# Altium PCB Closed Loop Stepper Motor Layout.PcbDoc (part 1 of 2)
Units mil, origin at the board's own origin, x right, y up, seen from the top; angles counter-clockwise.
Board outline 3560 x 2030 mil, 2 copper layers (Top Layer, Bottom Layer), stack 64.8 mil thick; 66 components, 54 nets, 285 pads, 203 vias.
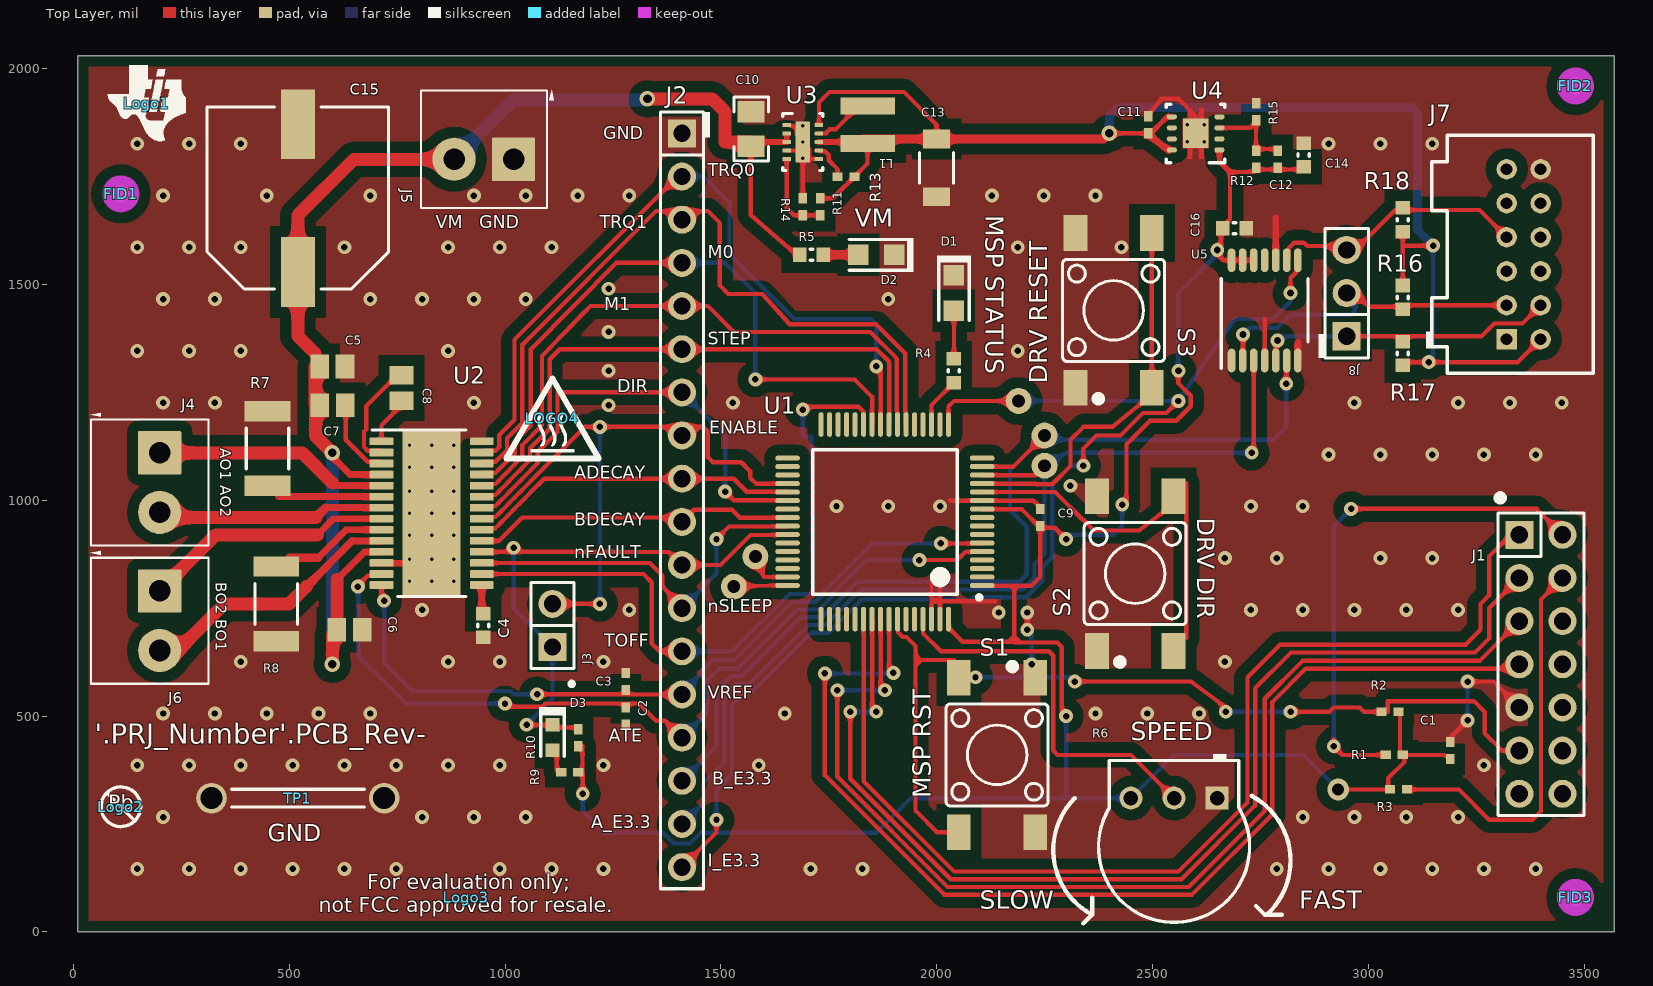
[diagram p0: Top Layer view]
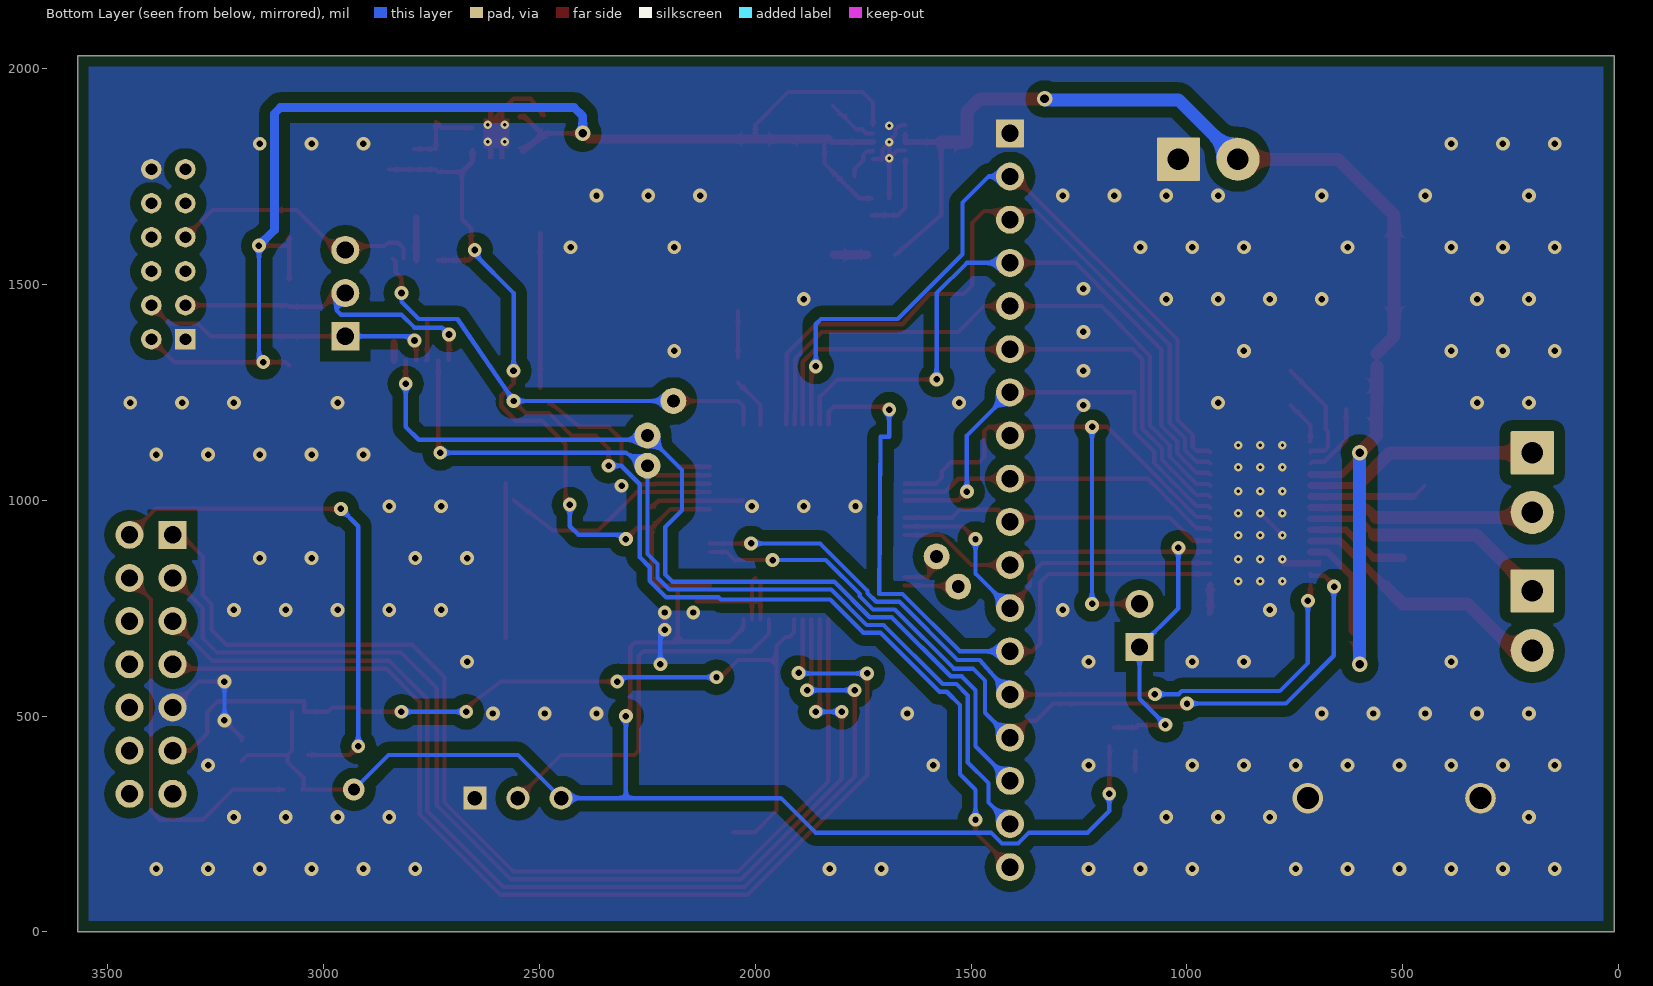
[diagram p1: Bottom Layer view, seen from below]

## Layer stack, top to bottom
Top Solder: solder mask 0.4, Solder Resist, Dk 3.5
Top Layer: signal copper 2.8
Dielectric1: core 59.2, FR-4, Dk 4.8
Bottom Layer: signal copper 2.8
Bottom Solder: solder mask 0.4, Solder Resist, Dk 3.5

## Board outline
10,0 10,2030 3570,2030 3570,0

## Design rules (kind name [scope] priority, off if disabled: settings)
AcuteAngle [All] p1: minimum=4.50000000000000E+0001 checktracksonly=FALSE
AssemblyTestPointUsage [All] p1: valid=2
BoardOutlineClearance BoardOutlineClearance_MountingHoles [OnCopper and InComponentClass('Mounting Holes')] p1: gap=40
BoardOutlineClearance BoardOutlineClearance_Poly [OnCopper and IsPoly] p2: gap=25
BoardOutlineClearance [OnCopper and Not InComponentClass('Logo') and not InComponentClass('FiducialMark') and not InRegion(1000,500,4000,800) and not InPoly] p3: gap=75
Clearance Clearance_Keepouts [((IsTrack Or IsArc) And Not InPoly) And IsFree and IsKeepOut vs ((IsTrack Or IsArc) And Not InPoly) And IsFree and IsKeepOut] p1: gap=0
Clearance Clearance_Poly [InPolygon] p2: gap=25
Clearance [All] p3: gap=7.87
ComponentClearance ComponentClearance_MountingHoles_FiducialMarks [InComponentClass('Mounting Holes') vs InComponentClass('FiducialMark')] p1: gap=50 collisioncheckmode=3 verticalgap=10 showdistances=FALSE
ComponentClearance ComponentClearance_Shunt [InComponentClass('Header') vs InComponentClass('Shunt')] p2: gap=0 collisioncheckmode=3 verticalgap=0 showdistances=FALSE
ComponentClearance ComponentClearance_Logo [InComponentClass('Logo')] p3: gap=50 collisioncheckmode=3 verticalgap=10 showdistances=FALSE
ComponentClearance ComponentClearance_ScrewToNut [(HasFootprint('NY PMS 440 0025 PH')) vs (HasFootprint('Keystone_1902C'))] p4: gap=5 collisioncheckmode=3 verticalgap=10 showdistances=FALSE
ComponentClearance ComponentClearance_MountingHoles [InComponentClass('Mounting Holes')] p5: gap=250 collisioncheckmode=3 verticalgap=100000 showdistances=FALSE
ComponentClearance ComponentClearance_SmallPassives [HasFootprint('0201*') or HasFootprint('0402*') or HasFootprint('0508') or HasFootprint('0603*') or HasFootprint('0612') or HasFootprint('0805*') or HasFootprint('0815*') or HasFootprint('0830*') or HasFootprint('1206*') or HasFootprint('1210*') or HasFootprint('1808*') or HasFootprint('1812*') or HasFootprint('1825*') or HasFootprint('2010*') or HasFootprint('2220*') or HasFootprint('2225*') or HasFootprint('2512*') or HasFootprint('2728*') or HasFootprint('3518*') vs HasFootprint('0201*') or HasFootprint('0402*') or HasFootprint('0508') or HasFootprint('0603*') or HasFootprint('0612') or HasFootprint('0805*') or HasFootprint('0815*') or HasFootprint('0830*') or HasFootprint('1206*') or HasFootprint('1210*') or HasFootprint('1808*') or HasFootprint('1812*') or HasFootprint('1825*') or HasFootprint('2010*') or HasFootprint('2220*') or HasFootprint('2225*') or HasFootprint('2512*') or HasFootprint('2728*') or HasFootprint('3518*')] p6: gap=14.96 collisioncheckmode=3 verticalgap=10 showdistances=FALSE
ComponentClearance ComponentClearance_THtoSMT [IsThruComponent vs IsSMTComponent] p7: gap=40 collisioncheckmode=3 verticalgap=30 showdistances=FALSE
ComponentClearance ComponentClearance_THtoTH [IsThruComponent vs IsThruComponent] p8: gap=30 collisioncheckmode=3 verticalgap=30 showdistances=FALSE
ComponentClearance [All] p9: gap=30 collisioncheckmode=3 verticalgap=10 showdistances=FALSE
DiffPairsRouting [All] p1: maxlimit=100 minlimit=10 mostfreqgap=10 toplayer_minwidth=15 toplayer_maxwidth=15 toplayer_prefwidth=15 bottomlayer_minwidth=15 bottomlayer_maxwidth=15 bottomlayer_prefwidth=15 maxuncoupledlength=1000
FabricationTestPointUsage TestPointUsage [All] p1: valid=2 allowmultiple=FALSE
FabricationTestpoint Testpoint [All] p1: side=3 testpointundercomponent=TRUE minsize=40 maxsize=100 preferedsize=60 minholesize=0 maxholesize=40 preferedholesize=32 testpointgrid=1 allowsidetop=TRUE allowsidebottom=TRUE usegrid=TRUE gridtolerance=0.01
FanoutControl Fanout_LCC [IsLCC] p1: bgadir=Out bgaviamode=Centered fanoutstyle=Auto fanoutdirection=Alternating viagrid=1 // Fanout_LCC (Default Rule)
FanoutControl Fanout_BGA [IsBGA] p2: bgadir=Out bgaviamode=Centered fanoutstyle=Auto fanoutdirection=Alternating viagrid=1 // Fanout_BGA (Default Rule)
FanoutControl Fanout_Default [All] p4: bgadir=Out bgaviamode=Centered fanoutstyle=Auto fanoutdirection=Alternating viagrid=1 // Fanout_Default (Default Rule)
FanoutControl Fanout_Small [(CompPinCount < 5)] p5: bgadir=Out bgaviamode=Centered fanoutstyle=Auto fanoutdirection=OutThenIn viagrid=1 // Fanout_Small (Default Rule)
HoleSize [All] p1: absolutevalues=TRUE maxlimit=251 minlimit=7.87 maxpercent=80.000 minpercent=20.000
MinimumAnnularRing MinimumAnnularRing_ThermalPadVias [IsVia and InAnyComponent] p1: minimumring=5.91
MinimumAnnularRing [All] p2: minimumring=8
MinimumSolderMaskSliver MinimumSolderMaskSliver_Logo [InComponentClass('Logo') vs InComponentClass('Logo')] p1: minsoldermaskwidth=0.7
MinimumSolderMaskSliver [All] p2: minsoldermaskwidth=3.94
PlaneConnect [All] p1: planeconnectstyle=Direct reliefexpansion=10 reliefentries=4 reliefconductorwidth=10 reliefairgap=10
PolygonConnect PolygonConnect_1 [All vs IsNamedPolygon('Top Layer-GND')] p1: connectstyle=Direct reliefconductorwidth=10 reliefentries=4 polygonreliefangle="90 Angle" airgapwidth=10
PolygonConnect [All] p2: connectstyle=Direct reliefconductorwidth=10 reliefentries=4 polygonreliefangle="90 Angle" airgapwidth=10
RoutingVias ThermalPadVias [IsVia and InAnyComponent] p1: holewidth=7.87 width=19.68 viastyle="Through Hole" minholewidth=7.87 minwidth=19.68 maxholewidth=12.99 maxwidth=23.62
RoutingVias [All] p2: holewidth=16 width=34 viastyle="Through Hole" minholewidth=7.87 minwidth=26 maxholewidth=40 maxwidth=65
SilkToBoardRegionClearance [Not ((IsComment or IsDesignator) And (Hide <> 'False')) and not InRegion(1000,500,4000,800)] p1:
SilkToSilkClearance SilkToSilkClearance_Pb-FreeLogo [(HasFootprint('Pb-Free_Overlay_Medium') OR HasFootprint('Pb-Free_Overlay_Small')) vs (HasFootprint('Pb-Free_Overlay_Medium') OR HasFootprint('Pb-Free_Overlay_Small'))] p1: silktosilkclearance=0
SilkToSilkClearance [All] p2: silktosilkclearance=4
SilkToSolderMaskClearance SilkToComponentPadClearance [IsPad and InAnycomponent] p1: minsilkscreentomaskgap=5 clearancetoexposedcopper=TRUE
SilkToSolderMaskClearance "Silk to Solder Mask Opening" [All] p2: minsilkscreentomaskgap=4 clearancetoexposedcopper=FALSE
SolderMaskExpansion [All] p1: expansion=1.97
Width [All] p1: maxlimit=100 minlimit=6 preferedwidth=10 checkconnectedcopper=TRUE
15 further rules are at their usual default settings.

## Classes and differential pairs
component class Header: J1 J2 J3 J8
component class "Closed Loop DRV8880_MSP430": C1 C2 C3 C4 C5 C6 C7 C8 C9 D1 D2 D3 J1 J2 J3 R1 R2 R3 R4 R5 R6 R7 R8 R9 R10 S1 S2 S3 U1 U2
component class "Closed Loop PWR&Encoder": 20 C10 C11 C12 C13 C14 C15 C16 J4 J5 J6 J7 J8 L1 R11 R12 R13 R14 R15 R16 R17 R18 Text TP1 U3 U4 U5
component class Logo: Logo1
component class "Closed Loop Last Sheet": FID1 FID2 FID3 Logo1 Logo2 Logo3 LOGO4 ZZ1 ZZ2 ZZ3 ZZ4
component class FiducialMark: FID1 FID2 FID3
component class AssemblyNote: ZZ1 ZZ2 ZZ3 ZZ4

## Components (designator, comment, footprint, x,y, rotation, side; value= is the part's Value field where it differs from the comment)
C1 "GRM155R61A104KA01D" 0402L 3190,420 r90 top
C2 "GRM155R61A104KA01D" 0402L 1280,500 r270 top
C3 "GRM155R61A104KA01D" 0402L 1280,580 r90 top
C4 "C0603C474K9RACTU" 0603L 950,710 r270 top
C5 "C0805C104K1RACTU" 0805L 600,1310 r0 top
C6 "C0805C104K1RACTU" 0805L 640,700 r0 top
C7 "0805YC474KAT2A" 0805L 600.47,1220 r180 top
C8 "GRM21BR71E104KA01L" 0805L 760,1260 r270 top
C9 "GRM155R61A104KA01D" 0402L 2240,960 r270 top
C10 "GRM21BR61E225KA12L" 0805_HV 1570,1860 r90 top
C11 "C1005X5R0J105M050BB" 0402L 2490,1870 r270 top
C12 "C1005C0G1H220J050BA" 0402L 2790,1790 r90 top
C13 "GRM31CR61A226ME19L" 1206_180 2000,1770 r270 top
C14 "GRM188R60J475KE19D" 0603L 2850,1800 r90 top
C15 "EEE-FK1J101P" SM_RADIAL_G 520,1700 r90 top
C16 "C0603C104K8RACTU" 0603L 2690,1630 r0 top
D1 "LTST-C171GKT" LED_LTST-C171 2040,1480 r90 top
D2 "LTST-C171GKT" LED_LTST-C171 1860,1568.7 r0 top
D3 "LTST-C190CKT" LED_LTST-C190_Red 1110,450 r90 top
FID1 "Fiducial" Fiducial10-20 110,1710 r0 top
FID2 "Fiducial" Fiducial10-20 3480,1960 r0 top
FID3 "Fiducial" Fiducial10-20 3480,80 r0 top
J1 "PEC07DAAN" CONN_PEC07DAAN 3400,620 r270 top
J2 "TSW-118-07-G-S" TSW-118-07-G-S 1410,1000 r270 top
J3 "Retry Mode DRV8880" CONN_90120-0122 1110,710 r90 top
J4 "AOUT" TERM_BLK_ED555-2DS 200,1110 r270 top
J5 "VM_GND" TERM_BLK_ED555-2DS 1020,1790 r180 top
J6 "BOUT" TERM_BLK_ED555-2DS 200,790 r270 top
J7 "B12B-PADSS-F(LF)(SN)" JST_B12B-PADSS-F 3360,1570 r90 top
J8 "TSW-103-07-G-S" TSW-103-07-G-S 2950,1480 r90 top
L1 "744025100" WE-TPC_2828 1840,1870 r270 top
Logo1 "Texas Instruments" TI_Symbol_Overlay_Small 170,1920 r0 top
Logo2 "Pb-Free Symbol" Pb-Free_Overlay_Small 110,290 r0 top
Logo3 "FCC disclaimer" FCC_disclaimer_stacked 910,80 r0 top
LOGO4 "CAUTION HOT SURFACE" IEC_HotSurface_Small 1110,1190 r0 top
R1 "ERJ-2GE0R00X" 0402L 3060,410 r0 top
R2 "CRCW04023K32FKED" 0402L 3050,510 r0 top
R3 "ERJ-2GE0R00X" 0402L 3070,330 r180 top
R4 "CRCW0603330RJNEA" 0603L 2040,1300 r270 top
R5 "CRCW060310K0JNEA" 0603L 1710,1568.7 r180 top
R6 "3352T-1-503LF" Bourns_3352T 2550,310 r180 top
R7 "CSRN2010FKR250" 2010L 450,1120 r270 top
R8 "CSRN2010FKR250" 2010L 470,760 r90 top
R9 "CRCW0402510RJNED" 0402L 1150,370 r0 top
R10 "CRCW04024K99FKED" 0402L 1170,450 r270 top
R11 "CRCW040280K6FKED" 0402L 1730,1680 r90 top
R12 "CRCW0402191KFKED" 0402L 2740,1790 r270 top
R13 "CRCW0402100KFKED" 0402L 1790,1750 r0 top
R14 "CRCW040215K4FKED" 0402L 1690,1680 r90 top
R15 "CRCW0402110KFKED" 0402L 2740,1900 r270 top
R16 "CRCW060310K0JNEA" 0603L 3080,1470 r90 top
R17 "CRCW060310K0JNEA" 0603L 3080,1340 r270 top
R18 "CRCW060310K0JNEA" 0603L 3080,1650 r270 top
S1 "4-1437565-1" SW_FSM4JSMA 2140,410 r0 top
S2 "4-1437565-1" SW_FSM4JSMA 2460,830 r180 top
S3 "4-1437565-1" SW_FSM4JSMA 2410,1440 r180 top
TP1 "D3082-05" Harwin_D3082-05 520,310 r180 top
U1 "MSP430F2617TPM" PM0064A_N 1880,950 r180 top
U2 "DRV8880PWPR" PWP0028C_N 830,970 r0 top
U3 "TPS62175DQCR" DQC0010A 1690,1830 r0 top
U4 "TPS73501DRBR" DRB0008A 2600,1850 r180 top
U5 "SN74LV4T125PWR" PW0014A_N 2760,1440 r90 top
ZZ1 "This Assembly Note is for PCB labels only" AssemblyNoteLabel 90,2270 r0 top
ZZ2 "These assemblies are ESD sensitive, ESD precautions shall be observed." AssemblyNote 90,2410 r0 top
ZZ3 "These assemblies must be clean and free from flux and all contaminants. Use of no clean flux is not acceptable." AssemblyNote 90,2550 r0 top
ZZ4 "These assemblies must comply with workmanship standards IPC-A-610 Class 2, unless otherwise specified." AssemblyNote 90,2710 r0 top

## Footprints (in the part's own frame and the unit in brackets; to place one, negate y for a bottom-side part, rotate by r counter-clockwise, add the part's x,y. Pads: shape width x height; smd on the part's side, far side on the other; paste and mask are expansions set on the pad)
0402L [mm] "0402 from SM-752 data"
  rect 0.6x0.5 smd: 1(-0.5,0) 2(0.5,0)
  body extent -0.55,-0.3 0.55,0.3, height 0.6
0603L [mm] "0603 from SM-752 data"
  rect 0.8x0.85 smd: 1(-0.7,0) 2(0.7,0)
  silkscreen extent -0.07,-0.33 0.07,0.33, body extent -0.87,-0.47 0.87,0.47, height 1
0805_HV [mil] "0805 with 30mil clearance between pads"
  rect 50x63 smd: 1(-40,0) 2(40,0)
  silkscreen extent -74,-40 74,40, body extent -43,-29 43,29, height 57
0805L [mm] "0805 from SM-752 data"
  rect 1.1x1.4 smd: 1(-0.75,0) 2(0.75,0)
  body extent -1.1,-0.72 1.1,0.72, height 1.45
1206_180 [mm] "1206_180"
  rect 1.1x1.6 smd: 1(-1.7,0) 2(1.7,0)
  silkscreen extent -0.9,-1 0.9,1, body extent -1.75,-0.95 1.75,0.95, height 1.8
2010L [mm]
  rect 1.2x2.7 smd: 1(-2.2,0) 2(2.2,0)
  silkscreen extent -1.2,-1.25 1.2,1.25, body extent -2.73,-1.45 2.73,1.45, height 1.66
AssemblyNote [mil] "Assembly Note"
AssemblyNoteLabel [mil] "Assembly Note for PCB Labels"
Bourns_3352T [mm] "TH, 3-Leads, Body 9.53x8.89mm, Pitch 2.54mm"
  rect 1.35x1.35 hole 0.85: 1(-2.54,0)
  round 1.35 hole 0.85: 2(0,0) 3(2.54,0)
  silkscreen extent -4.44,-2.6 4.44,7.31, body extent -4.44,-2.21 4.45,7.32, height 3.81
CONN_90120-0122 [mm] "Molex"
  rect 1.65x1.65 hole 1.016 mask+0: 1(-1.27,0)
  round 1.65 hole 1.016 mask+0: 2(1.27,0)
  silkscreen extent -3.56,-1.27 2.54,1.27, body extent -2.54,-1.27 2.54,1.27, height 9.29
CONN_PEC07DAAN [mm] "SULLINS"
  rect 1.65x1.65 hole 1.016 mask+0: 1(-7.62,-1.27)
  round 1.65 hole 1.016 mask+0: 2(-7.62,1.27) 3(-5.08,-1.27) 4(-5.08,1.27) 5(-2.54,-1.27) 6(-2.54,1.27) 7(0,-1.27) 8(0,1.27) 9(2.54,-1.27) 10(2.54,1.27) 11(5.08,-1.27) 12(5.08,1.27) 13(7.62,-1.27) 14(7.62,1.27)
  silkscreen extent -9.99,-2.6 8.89,2.54, body extent -8.95,-2.6 8.95,2.6, height 11.43
DQC0010A [mm] "SON, 10-Leads, Body 2.1x3.1mm, Pitch 0.5mm, Thermal Pad 2.4x0.8mm"
  rrect40% 0.5x0.25 smd: 1(-0.95,1) 2(-0.95,0.5) 3(-0.95,0) 4(-0.95,-0.5) 5(-0.95,-1) 6(0.95,-1) 7(0.95,-0.5) 8(0.95,0) 9(0.95,0.5) 10(0.95,1)
  rrect12% 0.8x1.08 on Top Paste: 11(0,-0.64) 11(0,0.64)
  rrect12% 0.84x2.4 smd paste-0.42: 11(0,0)
  silkscreen extent -1.17,-1.68 1.17,1.68, body extent -1,-1.5 1,1.5, height 0.77
DRB0008A [mm] "SON, 8-Leads, Body 3x3mm, Pitch 0.65mm, Thermal Pad 1.75x1.5mm, TI Recommended"
  oval 0.6x0.3 smd: 1(-1.4,0.975) 2(-1.4,0.325) 3(-1.4,-0.325) 4(-1.4,-0.975) 5(1.4,-0.975) 6(1.4,-0.325) 7(1.4,0.325) 8(1.4,0.975)
  rect 1.5x1.75 smd paste-0.75: 9(0,0)
  Top Layer region: -0.465,-1.5 -0.465,-0.875 -0.75,-0.875 -0.75,0.875 -0.465,0.875 -0.465,1.5 -0.185,1.5 -0.185,0.875 0.185,0.875 0.185,1.5 0.465,1.5 0.465,0.875 0.75,0.875 0.75,-0.875 0.465,-0.875 0.465,-1.5 0.185,-1.5 0.185,-0.875 -0.185,-0.875 -0.185,-1.5
  silkscreen extent -1.73,-1.73 1.73,1.73, body extent -1.57,-1.57 1.58,1.58, height 1.01
FCC_disclaimer_stacked [mil]
Fiducial10-20 [mm]
  round 1 smd mask+0.5: 1(0,0)
  Top Layer keep-out circle w1.178: c0,0 r0.5
Harwin_D3082-05 [mm] "Shorting Plug, 10.16mm spacing, TH"
  round 1.8 hole 1.3: 1(-5.08,0) 2(5.08,0)
  silkscreen extent -3.9,-0.53 3.9,0.53, body extent -5.6,-0.52 5.61,0.52, height 6.63
IEC_HotSurface_Small [mil]
  silkscreen extent -107,-93 107,92
JST_B12B-PADSS-F [mm] "Header(Shrouded), 2mm, 6x2, TH"
  rect 1.2x1.2 hole 0.7: 1(-5,1)
  round 1.2 hole 0.7: 2(-5,-1) 3(-3,1) 4(-3,-1) 5(-1,1) 6(-1,-1) 7(1,1) 8(1,-1) 9(3,1) 10(3,-1) 11(5,1) 12(5,-1)
  silkscreen extent -7,-4.1 7,5.75, body extent -7,-4.1 7,5.4, height 10.2
LED_LTST-C171 [mm] "LITE-ON"
  rect 1.2x1.2 smd: 1(-1.05,0) 2(1.05,0)
  silkscreen extent -1.6,-1 2.2,1, body extent -1.05,-0.67 1.05,0.67, height 0.8
LED_LTST-C190_Red [mm] "Lite-On"
  rect 0.8x0.8 smd: 1(-0.75,0) 2(0.75,0)
  silkscreen extent -1.1,-0.8 1.8,0.8, body extent -0.85,-0.45 0.85,0.45, height 0.9
Pb-Free_Overlay_Small [mil]
  silkscreen extent -46,-46 46,46
PM0064A_N [mm] "Thin QFP, 64-Leads, Body 10x10mm, Pitch 0.5mm, IPC Medium Density"
  oval 1.45x0.3 smd: 1(-5.725,3.75) 2(-5.725,3.25) 3(-5.725,2.75) 4(-5.725,2.25) 5(-5.725,1.75) 6(-5.725,1.25) 7(-5.725,0.75) 8(-5.725,0.25) 9(-5.725,-0.25) 10(-5.725,-0.75) 11(-5.725,-1.25) 12(-5.725,-1.75) 13(-5.725,-2.25) 14(-5.725,-2.75) 15(-5.725,-3.25) 16(-5.725,-3.75) 33(5.725,-3.75) 34(5.725,-3.25) 35(5.725,-2.75) 36(5.725,-2.25) 37(5.725,-1.75) 38(5.725,-1.25) 39(5.725,-0.75) 40(5.725,-0.25) 41(5.725,0.25) 42(5.725,0.75) 43(5.725,1.25) 44(5.725,1.75) 45(5.725,2.25) 46(5.725,2.75) 47(5.725,3.25) 48(5.725,3.75)
  oval 0.3x1.45 smd: 17(-3.75,-5.725) 18(-3.25,-5.725) 19(-2.75,-5.725) 20(-2.25,-5.725) 21(-1.75,-5.725) 22(-1.25,-5.725) 23(-0.75,-5.725) 24(-0.25,-5.725) 25(0.25,-5.725) 26(0.75,-5.725) 27(1.25,-5.725) 28(1.75,-5.725) 29(2.25,-5.725) 30(2.75,-5.725) 31(3.25,-5.725) 32(3.75,-5.725) 49(3.75,5.725) 50(3.25,5.725) 51(2.75,5.725) 52(2.25,5.725) 53(1.75,5.725) 54(1.25,5.725) 55(0.75,5.725) 56(0.25,5.725) 57(-0.25,5.725) 58(-0.75,5.725) 59(-1.25,5.725) 60(-1.75,5.725) 61(-2.25,5.725) 62(-2.75,5.725) 63(-3.25,5.725) 64(-3.75,5.725)
  silkscreen extent -5.68,-4.25 4.25,4.57, body extent -6,-6 6,6, height 1.49
PW0014A_N [mm] "TSOP, 14-Leads, Body 5x4.4mm, Pitch 0.65mm, IPC Medium Density"
  oval 1.4x0.45 smd: 1(-2.95,1.95) 2(-2.95,1.3) 3(-2.95,0.65) 4(-2.95,0) 5(-2.95,-0.65) 6(-2.95,-1.3) 7(-2.95,-1.95) 8(2.95,-1.95) 9(2.95,-1.3) 10(2.95,-0.65) 11(2.95,0) 12(2.95,0.65) 13(2.95,1.3) 14(2.95,1.95)
  silkscreen extent -3.4,-2.55 1.85,2.55, body extent -3.21,-2.5 3.21,2.5, height 1
PWP0028C_N [mm] "TSOP, 28-Leads, Body 9.7x4.4mm, Pitch 0.65mm, Exposed Pad, IPC Medium Density"
  rrect22% 1.4x0.45 smd: 1(-2.95,4.225) 2(-2.95,3.575) 3(-2.95,2.925) 4(-2.95,2.275) 5(-2.95,1.625) 6(-2.95,0.975) 7(-2.95,0.325) 8(-2.95,-0.325) 9(-2.95,-0.975) 10(-2.95,-1.625) 11(-2.95,-2.275) 12(-2.95,-2.925) 13(-2.95,-3.575) 14(-2.95,-4.225) 15(2.95,-4.225) 16(2.95,-3.575) 17(2.95,-2.925) 18(2.95,-2.275) 19(2.95,-1.625) 20(2.95,-0.975) 21(2.95,-0.325) 22(2.95,0.325) 23(2.95,0.975) 24(2.95,1.625) 25(2.95,2.275) 26(2.95,2.925) 27(2.95,3.575) 28(2.95,4.225)
  rrect3% 3.4x9.7 smd paste-1.7 mask-1.7: 29(0,0)
  rrect3% 3.1x5.18 on Top Paste: 29(0,0)
  rrect3% 3.1x5.18 on Top Solder: 29(0,0)
  silkscreen extent -3.5,-4.9 2,4.9, body extent -3.21,-4.85 3.21,4.85, height 0.98
SM_RADIAL_G [mm] "10 x 10.2mm:  Panasonic G"
  rect 4.1x2 smd: 1(-4.35,0) 2(4.35,0)
  silkscreen extent -5.35,-5.35 5.35,5.35, body extent -5.25,-5.25 5.25,5.25, height 10.5
SW_FSM4JSMA [mm] "Alcoswitch"
  rect 1.4x2.1 smd: 1(2.25,4.55) 2(2.25,-4.55) 3(-2.25,4.55) 4(-2.25,-4.55)
  silkscreen extent -3,-3 3,5.4, body extent -3,-5 3,5, height 5.1
TERM_BLK_ED555-2DS [mil]
  rrect4% 100x100 hole 50: 1(0,0)
  round 100 hole 50: 2(138,0)
  silkscreen extent -93,-161 215,113, body extent -69,-150 207,106, height 323
TI_Symbol_Overlay_Small [mil]
  silkscreen extent -90,-88 91,88
TSW-103-07-G-S [mm] "Samtec 100mil, 1x3, 230 mil above insulator"
  rect 1.65x1.65 hole 1.016: 1(-2.54,0)
  round 1.65 hole 1.016: 2(0,0) 3(2.54,0)
  silkscreen extent -3.81,-1.27 3.81,1.65, body extent -3.81,-1.27 3.81,1.27, height 8.38
TSW-118-07-G-S [mm] "Samtec 100mil, 1x18, 230 mil above insulator"
  rrect6% 1.65x1.65 hole 1.016: 1(-21.59,0)
  round 1.65 hole 1.016: 2(-19.05,0) 3(-16.51,0) 4(-13.97,0) 5(-11.43,0) 6(-8.89,0) 7(-6.35,0) 8(-3.81,0) 9(-1.27,0) 10(1.27,0) 11(3.81,0) 12(6.35,0) 13(8.89,0) 14(11.43,0) 15(13.97,0) 16(16.51,0) 17(19.05,0) 18(21.59,0)
  silkscreen extent -22.86,-1.27 22.86,1.65, body extent -22.86,-1.27 22.86,1.27, height 8.38
WE-TPC_2828 [mm] "WURTH"
  rect 1x3.2 smd: 1(-1.1,0) 2(1.1,0)
  body extent -1.5,-1.5 1.5,1.5, height 3

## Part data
C1 C2 C3 C9: "CAP, CERM, 0.1 µF, 10 V, +/- 10%, X5R, 0402"
C4: "CAP, CERM, 0.47 µF, 6.3 V, +/- 10%, X7R, 0603"
C5 C6: "CAP, CERM, 0.1 µF, 100 V, +/- 10%, X7R, 0805"
C7: "CAP, CERM, 0.47 µF, 16 V, +/- 10%, X7R, 0805"
C8: "CAP, CERM, 0.1 µF, 25 V, +/- 10%, X7R, 0805"
C10: "CAP, CERM, 2.2 µF, 25 V, +/- 10%, X5R, 0805"
C11: "CAP, CERM, 1 µF, 6.3 V, +/- 20%, X5R, 0402"
C12: "CAP, CERM, 22 pF, 50 V, +/- 5%, C0G/NP0, 0402"
C13: "CAP, CERM, 22 µF, 10 V, +/- 20%, X5R, 1206"
C14: "CAP, CERM, 4.7 µF, 6.3 V, +/- 10%, X5R, 0603"
C15: "CAP, AL, 100 µF, 63 V, +/- 20%, 0.35 ohm, AEC-Q200 Grade 2, SMD"
C16: "CAP, CERM, 0.1 µF, 10 V, +/- 10%, X7R, 0603"
D1 D2: "LED, Green, SMD"
D3: "LED, Red, SMD"
FID1 FID2 FID3: "Fiducial mark.  There is nothing to buy or mount."
J1: "Header, 100mil, 7x2, Tin, TH"
J2: "Header, 100mil, 18x1, Gold, TH"
J3: library part 90120-0122, "Header, 100mil, 2x1, Tin, TH"
J4 J5 J6: library part ED555/2DS, "Terminal Block, 3.5mm Pitch, 2x1, TH"
J7: "Header(Shrouded), 2mm, 6x2, Tin, TH"
J8: "Header, 100mil, 3x1, Gold, TH"
L1: "Inductor, Shielded Drum Core, Ferrite, 10 µH, 1 A, 0.17 ohm, SMD"
Logo1: library part TI_Logo, "Texas Instrument Corporate Signature"
Logo2: library part Pb-Free
Logo3: library part FCC_disclaimer, "FCC_disclaimer"
LOGO4: library part IEC_HotSurface, "IEC 61010-1 Hot Surface Warning"
R1 R3: "RES, 0, 5%, 0.063 W, 0402"
R2: "RES, 3.32 k, 1%, 0.063 W, 0402"
R4: "RES, 330, 5%, 0.1 W, 0603"
R5 R16 R17 R18: "RES, 10 k, 5%, 0.1 W, 0603"
R6: "Trimming Potentiometer, 50K, 0.5W, TH"
R7 R8: "RES, 0.25, 1%, 1 W, 2010"
R9: "RES, 510, 5%, 0.063 W, 0402"
R10: "RES, 4.99 k, 1%, 0.063 W, 0402"
R11: "RES, 80.6 k, 1%, 0.063 W, 0402"
R12: "RES, 191 k, 1%, 0.063 W, 0402"
R13: "RES, 100 k, 1%, 0.063 W, 0402"
R14: "RES, 15.4 k, 1%, 0.063 W, 0402"
R15: "RES, 110 k, 1%, 0.063 W, 0402"
S1 S2 S3: "Switch, Tactile, SPST-NO, 0.05A, 12V, SMT"
TP1: "1mm Uninsulated Shorting Plug, 10.16mm spacing, TH"
U1: "16 MHz Mixed Signal Microcontroller with 92 KB Flash, 8192 B SRAM and 48 GPIOs, -40 to 105 degC, 64-pin QFP (PM), Green (RoHS & no Sb/Br)"
U2: "2-A 45-V 1/16-µstep Stepper Motor Driver With AutoTune, PWP0028C (TSSOP-28)"
U3: "28V, 0.5A Step-Down Converter with Sleep Mode, DQC0010A (WSON-10)"
U4: "Single Output High PSRR LDO, 500 mA, Adjustable 1.25 to 6 V Output, 2.7 to 6.5 V Input, with Low IQ, 8-pin SON (DRB), -40 to 125 degC, Green (RoHS & no Sb/Br)"
U5: "Single Power Supply Quadruple Buffer Translator GATE With 3-State Output CMOS Logic Level Shifter, PW0014A (TSSOP-14)"
ZZ1: library part AssemblyNoteLabel
ZZ2 ZZ3 ZZ4: library part AssemblyNote

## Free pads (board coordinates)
  round 60 hole 30: 5(1580,870) 6(1530,800) 13(2190,1230) 14(2250,1150) 15(2250,1080)

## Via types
v1: diameter 32, hole 15, Top Layer to Bottom Layer, 165 vias
v2: diameter 19.68, hole 7.87, Top Layer to Bottom Layer, 16 vias
v3: diameter 19.68, hole 7.87, Top Layer to Bottom Layer, tented both sides, 12 vias
v4: diameter 36, hole 20, Top Layer to Bottom Layer, 4 vias
v5: diameter 32, hole 16, Top Layer to Bottom Layer, 3 vias
v6: diameter 32/32 (per signal layer), hole 16, Top Layer to Bottom Layer, 2 vias
v7: diameter 50, hole 28, Top Layer to Bottom Layer, 1 vias

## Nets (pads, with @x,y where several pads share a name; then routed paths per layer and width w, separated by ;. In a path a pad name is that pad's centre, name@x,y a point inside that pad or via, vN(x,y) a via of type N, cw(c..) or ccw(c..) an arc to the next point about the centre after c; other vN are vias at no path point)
3.3V_LDO: C1.1 C9.2 C12.1 C14.1 C16.1 R1.2 R2.2 R3.2 R6.3 R9.2 R10.2 R12.2 U1.1 U1.10 U1.64 U4.1 U5.12 U5.13 U5.14 | length 5161
  Top Layer w10: v1@1180,310.31 v1(1180,320) 1180,369.69 1179.69,370 1179.69,430 1180,430.31 ; U1.64@2027.64,724.61 2027.64,704.72 2060,672.36 2180,672.36 2180,802.13 ; U1.1@2105.39,802.36 2105.98,802.36 2106.89,803.27 2106.89,802.13 2180,802.13 ; U1.10@2105.39,979.53 2196.85,979.53 C9.2@2240,936.38 ; 2181.24,671.13 2280,670.1 2280,670 2290,660 v1@2290,510 ; v1(2300,910) 2273.62,936.38 C9.2@2240,936.38 ; v1@2440,1000 2440,1130 2494.18,1184.18 2555.01,1184.18 2588.87,1218.04 2588.87,1241.96 2560,1270.83 v5(2560,1300) ; v5(2650,1580) 2650,1570 2663.86,1556.14 U5.14@2683.23,1556.14 U5.13@2708.82,1556.14 U5.12@2734.41,1556.14 ; v5@2658.5,1580.87 2658.5,1630 2679.68,1651.18 2679.68,1760.32 R12.2@2736.06,1760.32 ; R12.2@2740,1766.38 C14.1@2847.87,1766.38 ; v7(2930,330) R3.2@3046.38,330 ; R3.2@3050.31,330 R3.2@3046.38,330 ; R2.2@3073.62,510 3073.62,420 R1.2@3083.62,410 ; C1.1@3190,396.38 3176.38,410 R1.2@3083.62,410 ; 2180,802.13 2220,802.13 2240,822.13 C9.2@2240,936.38 ; R3.2@3046.38,330 3046.38,356.38 3083.62,393.62 R1.2@3083.62,410
  Top Layer w12: U4.1@2655.12,1811.61 2655.12,1784.88 2679.68,1760.32
  Bottom Layer w10: v1(1180,320) 1180,280 1230,230 1365.86,230 1391.21,204.65 1428.79,204.65 1454.14,230 1860.83,230 1940.83,310 2300,310 ; v1(2300,500) 2300,310 ; v1@2310,920 2410,920 2430,940 v1(2430,990) ; v5(2560,1300) 2560,1480 2650,1570 v5(2650,1580) ; v7(2930,330) 2850,410 2550,410 R6.3@2450,310 2300,310
5V_BUCK: C11.2 C13.1 J7.2 L1.2 R11.2 R13.2 R16.2 R17.2 R18.2 U3.8 U3.10 U4.5 U4.8 | length 3379.8
  Top Layer w10: U3.10@1727.4,1869.37 1727.4,1921.59 1751.68,1945.87 1924.13,1945.87 2000,1870 C13.1@2000,1836.93 ; R11.2@1730,1699.68 1759.37,1699.68 1786.97,1727.28 1787.46,1727.28 1809.69,1749.51 R13.2@1809.69,1750 1840,1780.31 L1.2@1840,1826.69 ; L1.2@1823.31,1830 L1.2@1830.24,1836.93 ; 2386.93,1836.93 v4(2400,1850) 2489.19,1850 2495,1844.19 C11.2@2495,1845.31 ; R17.2@3080,1312.44 3087.56,1320 v1(3140,1320) 3346.22,1320 J7.2@3399.37,1373.15 ; R16.2@3080,1511.5 R18.2@3080,1609.37 ; 3080.31,1590 v1(3150,1590)
  Top Layer w12: C11.2@2492.24,1846.38 2534.25,1888.39 U4.5@2544.88,1888.39
  Top Layer w13: U3.8@1727.4,1830 L1.2@1823.31,1830
  Top Layer w16: C11.2@2492.24,1846.38 2494.45,1844.62 2495,1844.19 U4.8@2537.99,1810
  Top Layer w20: L1.2@1830.24,1836.93 C13.1@1997.26,1836.93 ; C13.1@2000,1836.93 2386.93,1836.93
  Bottom Layer w10: v1@3140,1330 v1(3140,1320) 3150,1330 v1(3150,1590)
  Bottom Layer w20: v4(2400,1850) 2400,1890 2420,1910 3100,1910 3114.13,1895.87 3114.13,1625.87 v1(3150,1590)
A_ENCODER_3.3V: J2.17 pad.15 U1.14 U5.3 | length 2290.7
  Top Layer w10: U1.14@2106.3,1059.17 U1.14@2105.39,1058.27 2228.27,1058.27 pad.15@2250,1080 ; v1@2734.41,1115.59 U5.3@2734.41,1323.86
  Bottom Layer w10: J2.17@1410,250 1460,300 1460,344.65 1507.87,392.52 1507.87,547.87 1534.25,574.25 1565.93,574.25 1702.86,711.18 1742.29,711.18 1824.36,793.25 2199.36,793.25 2226.75,820.64 2226.75,852.42 2250,875.67 pad.15@2250,1080 2300,1110 v1(2730,1110)
ADECAY: J2.9 U1.37 U2.20 | length 771.3
  Top Layer w10: U2.20@946.14,931.61 950,935.47 977.89,935.47 986.57,944.16 986.57,944.47 1004.45,962.34 1004.45,962.66 1022.32,980.53 1022.32,980.84 1040.2,998.72 1040.2,999.03 1058.07,1016.9 1058.07,1017.22 1090.85,1050 J2.9@1410,1050 1530,1050 1560.2,1019.8 1653.7,1019.8 U1.37@1654.61,1018.9
AENC_5V: J7.3 J8.2 R16.1 U5.2 | length 747.2
  Top Layer w10: U5.2@2710,1325.04 v6(2710,1383.86) ; J8.2@2970,1480 3001.5,1448.5 3080,1448.5 3083.39,1451.89 J7.3@3320.63,1451.89
  Bottom Layer w10: v6(2710,1383.86) 2726.14,1400 2790,1400 2820,1430 2960,1430 2970,1440 J8.2@2970,1480
AISEN: R7.2 U2.6 | length 274.4
  Top Layer w10: R7.2@450,1033.39 475,1008.39
  Top Layer w16: 475,1008.39 505,1008.39 573.72,1008.39 574,1008.67 595.43,1008.67 595.72,1008.39 U2.6@713.86,1008.39
AOUT1: J4.1 U2.5 | length 545.3
  Top Layer w10: 600,1040 606.02,1033.98
  Top Layer w16: 606.02,1033.98 U2.5@713.86,1033.98
  Top Layer w30: J4.1@200,1110 530,1110 600,1040
AOUT2: J4.2 U2.7 | length 528.6
  Top Layer w10: J4.2@200,972 J4.2@212,960 ; U2.7@713.64,982.58 U2.7@713.86,982.8
  Top Layer w16: 584.72,982.8 U2.7@713.86,982.8
  Top Layer w20: 561.92,960 584.72,982.8
  Top Layer w30: J4.2@212,960 561.92,960
AUTOTUNE: C2.1 J2.15 U1.5 U2.13 | length 1985
  Top Layer w10: v1@659.3,802.58 682.11,825.39 710,825.39 U2.13@713.86,829.25 U2.13@713.86,825.39 ; v1(1000,529.13) 1007.41,521.72 1086.19,521.72 1093.6,529.13 1310,529.13 1350,489.13 1370.87,489.13 J2.15@1410,450 ; v1(1960,861.42) 2044.81,861.42 2046.23,860 2066.43,880.2 U1.5@2104.49,880.2
  Bottom Layer w10: v1(659.3,799.94) 660,799.24 660,640 770.87,529.13 v1(1000,529.13) ; J2.15@1410,450 1467.87,507.87 1467.87,582.13 1495.73,610 1540.01,610 1676.94,746.93 1727.48,746.93 1757.87,777.32 1757.87,782.68 1835.2,860 1836.61,861.42 v1(1960,861.42)
B_ENCODER_3.3V: J2.16 pad.14 U1.15 U5.6 | length 2349.6
  Top Layer w10: U1.15@2105.39,1077.95 2177.95,1077.95 pad.14@2250,1150 ; v1(2810,1270) 2810,1322.68 U5.6@2811.18,1323.86
  Bottom Layer w10: J2.16@1410,350 1490,430 1490,560 1522.13,592.13 1547.41,592.13 1684.34,729.06 1734.89,729.06 1816.96,811.13 2191.96,811.13 2208.87,828.04 2208.87,937.87 2170,976.75 2170,1070 pad.14@2250,1150 2260,1140 2780,1140 2810,1170 v1(2810,1270)
BDECAY: J2.10 U1.40 U2.19 | length 771.9
  Top Layer w10: U2.19@946.14,906.02 986.02,906.02 1040,960 1400,960 J2.10@1410,950 1437.87,977.87 1525.69,977.87 1543.72,959.84 U1.40@1654.61,959.84 ; J2.10@1410,960 J2.10@1410,977.87
BENC_5V: J7.4 J8.1 R17.1 U5.5 | length 660.9
  Top Layer w10: U5.5@2785.59,1323.86 v6@2785.59,1365.59 ; J8.1@2980,1380 3262.03,1380 3291.68,1409.65 3357.13,1409.65 J7.4@3399.37,1451.89
  Bottom Layer w10: v6@2800,1380 J8.1@2970,1380
  other v6: 2790,1370
BISEN: R8.2 U2.9 | length 240.8
  Top Layer w16: 566.61,866.61 631.61,931.61 U2.9@713.86,931.61
  Top Layer w20: R8.2@500,866.61 566.61,866.61
BOUT1: J6.2 U2.10 | length 624.5
  Top Layer w10: J6.2@200,652 J6.2@242,652 ; U2.10@710,902.17 U2.10@713.86,906.02
  Top Layer w16: 646.02,906.02 U2.10@713.86,906.02
  Top Layer w18: 540,800 646.02,906.02
  Top Layer w30: J6.2@242,652 350,760 500,760 540,800
BOUT2: J6.1 U2.8 | length 583.1
  Top Layer w16: 565.59,920 602.8,957.2 U2.8@713.86,957.2
  Top Layer w30: J6.1@200,790 330,920 540,920 565.59,920
DIR: J2.7 U1.38 U2.22 | length 1097.6
  Top Layer w10: U2.22@946.14,982.8 950,986.65 977.89,986.65 986.57,995.34 986.57,995.65 1004.45,1013.52 1004.45,1013.84 1022.32,1031.71 1022.32,1032.02 1040.2,1049.9 1040.2,1050.21 1058.07,1068.08 1058.07,1068.4 1075.94,1086.27 1075.94,1112.6 1121.5,1158.15 1121.5,1250 J2.7@1390,1250 ; J2.7@1410,1250 J2.7@1390,1250 ; J2.7@1410,1270 J2.7@1390,1250 ; v1(1510,1020) 1529.88,1000.12 1653.7,1000.12 U1.38@1654.61,999.21
  Bottom Layer w10: J2.7@1410,1250 1510,1150 v1(1510,1020)
DRV_DIR: S2.3 S2.4 U1.12 | length 874.5
  Top Layer w10: U1.12@2105.39,1018.9 2105.75,1019.25 2275.16,1019.25 2275.16,1018.28 2338.53,954.92 2339.49,954.92 2364.41,930 2469.45,930 S2.4@2560,1000 ; 2578.58,680.87 2578.58,1039.13
DRV_RESET: S3.3 S3.4 U1.13 | length 843.6
  Top Layer w10: U1.13@2105.39,1038.58 2230.78,1038.58 ; 2232.24,1037.13 2267.76,1037.13 2310,1079.37 2310,1140 2340,1170 2407.72,1170 S3.3@2480,1230 ; S3.3@2498.58,1260.87 S3.4@2498.58,1619.13
ENABLE: J2.8 J3.2 U1.36 U2.21 | length 1417.5
  Top Layer w10: U2.21@946.14,957.2 950,961.06 977.89,961.06 986.57,969.75 986.57,970.06 1004.45,987.93 1004.45,988.25 1022.32,1006.12 1022.32,1006.43 1040.2,1024.31 1040.2,1024.62 1058.07,1042.49 1058.07,1042.81 1075.94,1060.68 1075.94,1060.99 1184.95,1170 1460,1170 1470,1160 1470,1100 1482.13,1087.87 1547.4,1087.87 1567.87,1067.4 1567.87,1052.13 1581.42,1038.58 U1.36@1654.61,1038.58 U1.36@1653.7,1039.49 ; J3.2@1110,760 v1(1220,760)
  Bottom Layer w10: v1(1220,760) v1(1220,1170)
GND: C1.2 C2.2 C3.2 C4.2 C5.2 C6.2 C9.1 C10.2 C11.1 C13.2 C14.2 C15.2 C16.2 D1.2 D2.2 J1.9 J2.1 J5.1 J7.1 J7.12 R6.1 R7.1 R8.1 R14.2 R15.1 S1.1 S1.2 S2.1 S2.2 S3.1 S3.2 TP1.1 TP1.2 U1.11 U1.62 U1.63 U2.12 U2.28 U2.29@830,970 U3.1 U3.4 U3.6 U3.11@1690,1830 U4.4 U4.9 U5.1 U5.4 U5.7 U5.10 | length 1765.1
  Top Layer w10: U2.12@713.86,854.84 U2.12@717.72,858.7 ; v2(778.82,918.82) v2(830,970) ; U3.4@1652.6,1810.32 1672.28,1810.32 v2(1690,1792.6) ; U3.1@1652.6,1869.37 1659.53,1869.37 1661.42,1867.48 1666.62,1867.48 1675.32,1858.79 1675.32,1846.65 1690,1831.97 v2(1690,1830) U3.11@1690,1827.95 ; R14.2@1690,1699.68 v2(1690,1792.6) ; U3.6@1727.4,1790.63 1704.69,1790.55 1704.69,1813.27 U3.11@1690,1827.95 ; U1.62@1988.27,724.61 1988.27,811.73 ; 2000,820 2007.95,812.05 2007.95,760.17 ; U1.63@2007.95,724.61 2007.95,760.17 ; 2030,1000 2030.79,999.21 U1.11@2105.39,999.21 2224.41,999.21 C9.1@2240,983.62 ; 2136.02,766.02 2013.8,766.02 2007.95,760.17 ; v1(2210,700) v1(2210,740) ; C11.1@2490,1891.63 2520,1930 2560,1930 2600,1890 U4.9@2600,1850 ; 2760,1420.31 U5.4@2760,1323.86 U5.4@2763.86,1323.86 ; C1.2@3190,443.62 3190,450 v1(3230,490) ; v1(3230,580) 3290,580 J1.9@3350,520 ; v2(1690,1792.6) U3.11@1690,1827.95
  Top Layer w16: U5.10@2785.59,1556.14 2785.59,1654.41 ; U5.7@2836.77,1323.86 2836.77,1365.26
  Bottom Layer w10: v1(2143.78,740) v1@2143.78,743.78 ; v1(2210,700) 2220,690 v1(2220,620) ; v1(3230,490) v1(3230,580)
  other v1: 148,146 268,146 388,146 508,146 628,146 748,146 988,146 1108,146 1228,146 1708,146 1828,146 2788,146 2908,146 3028,146 3148,146 3268,146 3388,146 208,266 808,266 928,266 1048,266 2848,266 2968,266 3088,266 3208,266 148,386 268,386 388,386 508,386 628,386 748,386 868,386 988,386 1228,386 1588,386 3268,386 208,506 328,506 448,506 568,506 688,506 1648,506 2368,506 2488,506 2608,506 388,626 868,626 988,626 1228,626 2668,626 808,746 1288,746 2728,746 2848,746 2968,746 3088,746 3208,746 2668,866 2788,866 3028,866 3148,866 1768,986 1888,986 2008,986 2728,986 2848,986 2310,1033.45 2908,1106 3028,1106 3148,1106 3268,1106 3388,1106 1240,1220 208,1226 328,1226 928,1226 1528,1226 2968,1226 3208,1226 3328,1226 3448,1226 1240,1300 148,1346 268,1346 388,1346 868,1346 2188,1346 1240,1390 208,1466 328,1466 688,1466 808,1466 928,1466 1048,1466 1888,1466 1240,1490 148,1586 268,1586 388,1586 628,1586 868,1586 988,1586 1108,1586 2188,1586 2428,1586 208,1706 448,1706 688,1706 928,1706 1048,1706 1168,1706 1288,1706 2128,1706 2248,1706 2368,1706 148,1826 268,1826 388,1826 2908,1826 3028,1826 3148,1826
  other v2: 830,918.82 881.18,918.82 778.82,970 881.18,970 778.82,1021.18 830,1021.18 881.18,1021.18 2580.32,1830.32 2619.68,1830.32 1690,1867.4 2580.32,1869.68 2619.68,1869.68
  other v3: 778.82,812.52 830,812.52 881.18,812.52 778.82,863.7 830,863.7 881.18,863.7 778.82,1076.3 830,1076.3 881.18,1076.3 778.82,1127.48 830,1127.48 881.18,1127.48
